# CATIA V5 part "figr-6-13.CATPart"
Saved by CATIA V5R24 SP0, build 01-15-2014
Part number: Part1
Bounding box of the stored display mesh (mm): x -25 to 25, y -75 to 75, z 0 to 20
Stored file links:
  D:\KAVITA\CATIA V5-6R2014 Project_ Kavita\CATIA V5-6R2014_partfiles\Partfiles\c06_catia_v5-6r2014_prt\figr-6-13.CATPart
  C:\Program Files\Dassault Systemes\B13\intel_a\reffiles\standard\MetricThinPitch.txt
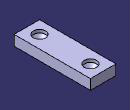
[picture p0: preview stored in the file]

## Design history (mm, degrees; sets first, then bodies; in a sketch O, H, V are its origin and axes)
Body1 (main body)
  Sketch1 on xy-plane, origin (0, 0, 0), H (1, 0, 0), V (0, 1, 0)
    line L1 (-25, 75) -> (25, 75)
    line L2 (25, 75) -> (25, -75)
    line L3 (25, -75) -> (-25, -75)
    line L4 (-25, -75) -> (-25, 75)
    axis line L5 (25, -75) -> (-25, 75)
    length L2 = 150
    length L3 = 50
    horizontal: L1 H, L3 H
    vertical: L2 V, L4 V
    midpoint: O L5
  Pad1: profile Sketch1, direction (0, 0, 1), length 20
  Sketch2 on face of Pad1, origin (-8.6664, -28.8348, 20), H (1, 0, 0), V (0, 1, 0)
    point P1 (8.6664, -21.1652)
    reference projected line E1 (-16.3336, -46.1652) -> (33.6664, -46.1652) from edge [face of Pad1 | face of Pad1]
    reference projected line E2 (-16.3336, 103.8348) -> (-16.3336, -46.1652) from edge [face of Pad1 | face of Pad1]
    distance P1 E1 = 25
    distance P1 E2 = 25
  Hole1: placed by Sketch2, at (0, -50, 20) direction (0, 0, -1), diameter 10.647, through (limit type 3), type CounterDrilledType, Diameter 10.647, DiameterThread 12, Pas 1.25, Profile a sketch, Sketch Sketch2, ThreadDepth 10, ThreadDescription "M12", Angle 90, Depth 6, Diameter 24
  Sketch3 on face of Pad1, origin (3.6925, 50.8892, 20), H (1, 0, 0), V (0, 1, 0)
    point P1 (-3.6925, -0.8892)
    reference projected line E1 (-28.6925, 24.1108) -> (-28.6925, -125.8892) from edge [face of Pad1 | face of Pad1]
    reference projected line E2 (21.3075, 24.1108) -> (-28.6925, 24.1108) from edge [face of Pad1 | face of Pad1]
    distance P1 E1 = 25
    distance E2 P1 = 25
  Hole2: placed by Sketch3, at (0, 50, 20) direction (0, 0, -1), diameter 10.647, through (limit type 3), type CounterDrilledType, Diameter 10.647, DiameterThread 11.7117, Pas 1, Profile a sketch, Sketch Sketch3, ThreadDepth 10, Angle 90, Depth 6, Diameter 24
